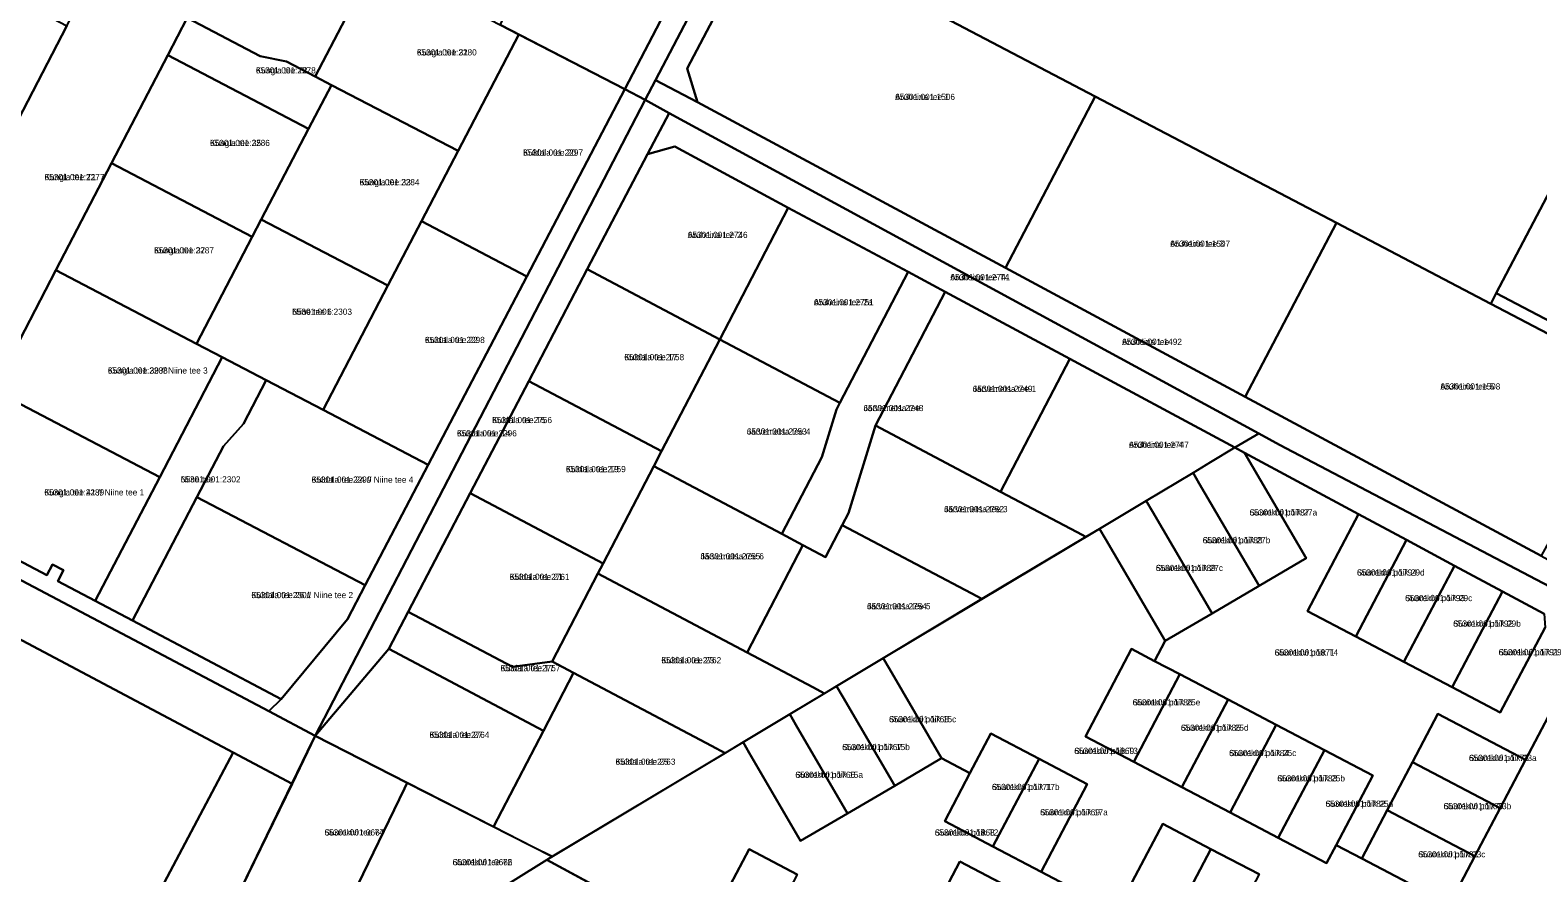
# Model space of a CAD drawing. Extents: x 543236 to 563717, y 6566033 to 6588992.
# Drawn here: x 545424.5 to 545789.8, y 6585039 to 6585243.3 of the extents above; entities that cross this region are included whole.
import ezdxf

# ---------------------------------------------------------------- set-up
doc = ezdxf.new("R2010")
doc.units = 0
for name, color, linetype in [('L_AADRESS', 7, 'Continuous'), ('PIIR', 7, 'Continuous'), ('TUNNUS', 7, 'Continuous')]:
    doc.layers.add(name, color=color, linetype=linetype)

msp = doc.modelspace()

# ---------------------------------------------------------------- linework, layer by layer
at = {"layer": 'PIIR'}
for points in [[(545810.82, 6585238.87), (545779.7, 6585179.53), (545778.37, 6585177), (545741, 6585196.59), (545682.55, 6585227.24), (545645.88, 6585246.47), (545647.21, 6585249.01), (545678.33, 6585308.34), (545709.67, 6585368.12), (545717.64, 6585363.94), (545697.05, 6585324.68), (545770.56, 6585286.13), (545782.51, 6585308.92), (545737.33, 6585384.25), (545731.7, 6585373.51), (545724.61, 6585377.23), (545720.43, 6585369.26), (545712.47, 6585373.43), (545743.84, 6585433.2)], [(545791.29, 6585101.79), (545781.2, 6585107.22), (545769.57, 6585113.48), (545757.95, 6585119.74), (545746.33, 6585126), (545718.68, 6585140.88), (545716.37, 6585142.12), (545722.15, 6585145.58), (545727.2, 6585142.83), (545794.29, 6585107.55)], [(545793.06, 6585078.35), (545786.77, 6585066.38), (545765.53, 6585077.56), (545759.38, 6585065.87), (545753.24, 6585054.19), (545747.1, 6585042.51), (545740.9, 6585045.76), (545749.75, 6585062.58), (545738.06, 6585068.72), (545726.38, 6585074.87), (545714.7, 6585081.01), (545703.02, 6585087.16), (545696.9, 6585090.37), (545699.46, 6585095.24), (545710.84, 6585101.92), (545722.22, 6585108.61), (545733.61, 6585115.29), (545718.68, 6585140.88), (545746.33, 6585126), (545733.95, 6585102.45), (545745.63, 6585096.31), (545757.31, 6585090.16), (545768.99, 6585084.02), (545780.68, 6585077.87), (545791.54, 6585098.53)], [(545722.25, 6585038.66), (545710.56, 6585044.78), (545698.87, 6585050.92), (545687.69, 6585029.64), (545669.41, 6585039.22), (545680.61, 6585060.53), (545668.93, 6585066.67), (545657.25, 6585072.81), (545652.18, 6585063.17), (545645.31, 6585066.78), (545632.67, 6585088.45), (545631.15, 6585091.04), (545683.58, 6585122.46), (545685.09, 6585119.87), (545699.46, 6585095.24), (545696.9, 6585090.37), (545691.33, 6585093.3), (545680.16, 6585072.06), (545691.85, 6585065.92), (545703.53, 6585059.77), (545715.21, 6585053.63), (545726.89, 6585047.48), (545738.58, 6585041.34), (545740.9, 6585045.76), (545747.1, 6585042.51), (545768.34, 6585031.33)], [(545796.96, 6585037.66), (545770.02, 6584986.31), (545766.77, 6584980.11), (545760.64, 6584968.42), (545754.51, 6584956.73), (545748.38, 6584945.04), (545745.2, 6584938.99), (545735.06, 6584944.32), (545725.29, 6584949.46), (545714.15, 6584953.57), (545719.21, 6584957.4), (545726.9, 6584963.24), (545735.97, 6584980.49), (545740.39, 6584978.17), (545746.53, 6584989.85), (545752.67, 6585001.54), (545758.81, 6585013.22), (545768.34, 6585031.33), (545774.48, 6585043.02), (545780.63, 6585054.7), (545786.77, 6585066.38), (545793.06, 6585078.35)], [(545586.73, 6585022.12), (545549.62, 6585042.17), (545597.19, 6585070.68), (545598.7, 6585068.09), (545611.14, 6585046.77), (545622.54, 6585053.42), (545633.93, 6585060.1), (545645.31, 6585066.78), (545652.18, 6585063.17), (545646.05, 6585051.51), (545657.73, 6585045.37), (545669.41, 6585039.22), (545687.69, 6585029.64)], [(545610.33, 6585038.63), (545598.65, 6585044.77), (545587.93, 6585024.39)]]:
    msp.add_lwpolyline(points, dxfattribs=at)
for points in [[(545576.01, 6585231.19), (545655.16, 6585382.35), (545660.23, 6585379.39), (545678.51, 6585414.04), (545681.17, 6585412.64), (545671.71, 6585394.8), (545668.91, 6585389.49), (545663.77, 6585379.74), (545650.9, 6585355.37), (545648.25, 6585356.76), (545634.76, 6585331.19), (545603.5, 6585271.93), (545601, 6585267.13), (545583.64, 6585234.01), (545586.14, 6585225.85)], [(545573.51, 6585226.42), (545568.52, 6585229.01), (545590.66, 6585271.51), (545596.2, 6585282.16), (545612.83, 6585314.09), (545631.44, 6585349.49), (545650.21, 6585385.19), (545655.16, 6585382.35), (545576.01, 6585231.19)], [(545455.85, 6585287.6), (545478.02, 6585276.05), (545462.53, 6585246.3), (545457.82, 6585237.26), (545444.19, 6585211.09), (545430.7, 6585185.18), (545415.55, 6585156.09), (545399.99, 6585126.22), (545377.89, 6585137.91), (545394.95, 6585170.65), (545416.76, 6585212.53), (545433.36, 6585244.41), (545438.07, 6585253.45)], [(545538.33, 6585244.64), (545560.5, 6585287.22), (545590.66, 6585271.51), (545568.52, 6585229.01)], [(545478.02, 6585276.05), (545508.18, 6585260.35), (545493.48, 6585232.12), (545486.61, 6585235.72), (545480.17, 6585237.06), (545462.53, 6585246.3)], [(545601, 6585267.13), (545629.11, 6585252.39), (545630.3, 6585254.64), (545645.88, 6585246.47), (545682.55, 6585227.24), (545660.76, 6585185.7), (545586.14, 6585225.85), (545583.64, 6585234.01)], [(545402.76, 6585260.48), (545433.36, 6585244.41), (545416.76, 6585212.53), (545386.12, 6585228.55)], [(545508.18, 6585260.35), (545538.33, 6585244.64), (545542.85, 6585242.29), (545528.15, 6585214.06), (545497.44, 6585230.04), (545493.48, 6585232.12)], [(545462.53, 6585246.3), (545480.17, 6585237.06), (545486.61, 6585235.72), (545493.48, 6585232.12), (545497.44, 6585230.04), (545491.9, 6585219.4), (545457.82, 6585237.26)], [(545542.85, 6585242.29), (545568.52, 6585229.01), (545544.79, 6585183.6), (545519.29, 6585197.06), (545528.15, 6585214.06)], [(545779.7, 6585179.53), (545810.82, 6585238.87), (545852.8, 6585216.85), (545855.46, 6585215.46), (545824.53, 6585156.02)], [(545457.82, 6585237.26), (545491.9, 6585219.4), (545480.44, 6585197.4), (545478.27, 6585193.23), (545444.19, 6585211.09)], [(545497.44, 6585230.04), (545528.15, 6585214.06), (545519.29, 6585197.06), (545511.15, 6585181.42), (545480.44, 6585197.4), (545491.9, 6585219.4)], [(545573.51, 6585226.42), (545576.01, 6585231.19), (545586.14, 6585225.85), (545660.76, 6585185.7), (545718.88, 6585154.42), (545790.6, 6585115.84), (545795.45, 6585113.23), (545805.7, 6585107.83), (545803.14, 6585102.9), (545794.29, 6585107.55), (545727.2, 6585142.83), (545722.15, 6585145.58), (545579.26, 6585223.25)], [(545196.2, 6585229.84), (545231.09, 6585211.25), (545291.43, 6585179.1), (545482.25, 6585078.21), (545493.54, 6585072.24), (545487.93, 6585060.63), (545473.62, 6585068.23), (545384.58, 6585115.49), (545368.67, 6585123.92), (545196.85, 6585214.99)], [(545568.52, 6585229.01), (545573.51, 6585226.42), (545493.54, 6585072.24), (545482.25, 6585078.21), (545485.31, 6585081.11), (545501.37, 6585100.52), (545505.66, 6585108.74), (545520.92, 6585137.92), (545544.79, 6585183.6)], [(545573.51, 6585226.42), (545579.26, 6585223.25), (545574.05, 6585213.28), (545559.45, 6585185.35), (545545.3, 6585158.27), (545531.1, 6585131.11), (545516.06, 6585102.34), (545511.34, 6585093.29), (545493.54, 6585072.24)], [(545660.76, 6585185.7), (545682.55, 6585227.24), (545741, 6585196.59), (545718.88, 6585154.42)], [(545579.26, 6585223.25), (545722.15, 6585145.58), (545716.37, 6585142.12), (545676.36, 6585163.64), (545646.17, 6585179.87), (545637.19, 6585184.71), (545608.13, 6585200.3), (545580.63, 6585215.14), (545574.05, 6585213.28)], [(545574.05, 6585213.28), (545580.63, 6585215.14), (545608.13, 6585200.3), (545591.53, 6585168.36), (545559.45, 6585185.35)], [(545444.19, 6585211.09), (545478.27, 6585193.23), (545464.78, 6585167.32), (545430.7, 6585185.18)], [(545480.44, 6585197.4), (545511.15, 6585181.42), (545495.44, 6585151.26), (545481.65, 6585158.49), (545471.02, 6585164.06), (545464.78, 6585167.32), (545478.27, 6585193.23)], [(545608.13, 6585200.3), (545637.19, 6585184.71), (545620.68, 6585152.94), (545591.53, 6585168.36)], [(545519.29, 6585197.06), (545544.79, 6585183.6), (545520.92, 6585137.92), (545495.44, 6585151.26), (545511.15, 6585181.42)], [(545718.88, 6585154.42), (545741, 6585196.59), (545778.37, 6585177), (545793.96, 6585168.82), (545792.78, 6585166.57), (545822.04, 6585151.22), (545803.95, 6585116.5), (545793.81, 6585121.8), (545790.6, 6585115.84)], [(545293.31, 6585182.63), (545295.64, 6585181.4), (545297.17, 6585184.32), (545299.87, 6585182.89), (545298.35, 6585179.97), (545347.41, 6585154.07), (545377.89, 6585137.91), (545399.99, 6585126.22), (545428.49, 6585111.16), (545429.86, 6585113.8), (545432.56, 6585112.37), (545431.19, 6585109.73), (545440.23, 6585104.95), (545449.25, 6585100.18), (545485.31, 6585081.11), (545482.25, 6585078.21), (545291.43, 6585179.1), (545291.9, 6585179.98)], [(545430.7, 6585185.18), (545464.78, 6585167.32), (545471.02, 6585164.06), (545455.86, 6585134.97), (545415.55, 6585156.09)], [(545559.45, 6585185.35), (545591.53, 6585168.36), (545577.44, 6585141.26), (545545.3, 6585158.27)], [(545637.19, 6585184.71), (545646.17, 6585179.87), (545629.32, 6585147.46), (545622.74, 6585126.23), (545621.23, 6585123.34), (545617.21, 6585115.59), (545611.71, 6585118.5), (545606.61, 6585121.2), (545616.27, 6585139.79), (545619.85, 6585151.34), (545620.68, 6585152.94)], [(545646.17, 6585179.87), (545676.36, 6585163.64), (545659.61, 6585131.42), (545629.32, 6585147.46)], [(545778.37, 6585177), (545779.7, 6585179.53), (545824.53, 6585156.02), (545822.04, 6585151.22), (545792.78, 6585166.57), (545793.96, 6585168.82)], [(545591.53, 6585168.36), (545620.68, 6585152.94), (545619.85, 6585151.34), (545616.27, 6585139.79), (545606.61, 6585121.2), (545575.56, 6585137.63), (545577.44, 6585141.26)], [(545471.02, 6585164.06), (545481.65, 6585158.49), (545476.13, 6585147.91), (545471.27, 6585142.46), (545464.84, 6585130.13), (545449.25, 6585100.18), (545440.23, 6585104.95), (545455.86, 6585134.97)], [(545676.36, 6585163.64), (545716.37, 6585142.12), (545710.48, 6585138.59), (545706.22, 6585136.03), (545694.9, 6585129.25), (545683.58, 6585122.46), (545680.28, 6585120.49), (545678.18, 6585121.6), (545659.61, 6585131.42)], [(545481.65, 6585158.49), (545495.44, 6585151.26), (545520.92, 6585137.92), (545505.66, 6585108.74), (545464.84, 6585130.13), (545471.27, 6585142.46), (545476.13, 6585147.91)], [(545545.3, 6585158.27), (545577.44, 6585141.26), (545575.56, 6585137.63), (545563.31, 6585114.06), (545531.1, 6585131.11)], [(545415.55, 6585156.09), (545455.86, 6585134.97), (545440.23, 6585104.95), (545431.19, 6585109.73), (545432.56, 6585112.37), (545429.86, 6585113.8), (545428.49, 6585111.16), (545399.99, 6585126.22)], [(545629.32, 6585147.46), (545659.61, 6585131.42), (545678.18, 6585121.6), (545680.28, 6585120.49), (545655.05, 6585105.45), (545652.5, 6585106.8), (545621.23, 6585123.34), (545622.74, 6585126.23)], [(545706.22, 6585136.03), (545710.48, 6585138.59), (545716.37, 6585142.12), (545718.68, 6585140.88), (545733.61, 6585115.29), (545722.22, 6585108.61), (545707.73, 6585133.44)], [(545575.56, 6585137.63), (545606.61, 6585121.2), (545611.71, 6585118.5), (545598.16, 6585092.42), (545562, 6585111.56), (545563.31, 6585114.06)], [(545694.9, 6585129.25), (545706.22, 6585136.03), (545707.73, 6585133.44), (545722.22, 6585108.61), (545710.84, 6585101.92), (545696.41, 6585126.66)], [(545464.84, 6585130.13), (545505.66, 6585108.74), (545501.37, 6585100.52), (545485.31, 6585081.11), (545449.25, 6585100.18)], [(545531.1, 6585131.11), (545563.31, 6585114.06), (545562, 6585111.56), (545550.92, 6585090.24), (545541.34, 6585088.96), (545516.06, 6585102.34)], [(545683.58, 6585122.46), (545694.9, 6585129.25), (545696.41, 6585126.66), (545710.84, 6585101.92), (545699.46, 6585095.24), (545685.09, 6585119.87)], [(545746.33, 6585126), (545757.95, 6585119.74), (545745.63, 6585096.31), (545733.95, 6585102.45)], [(545611.71, 6585118.5), (545617.21, 6585115.59), (545621.23, 6585123.34), (545652.5, 6585106.8), (545655.05, 6585105.45), (545631.15, 6585091.04), (545619.83, 6585084.25), (545616.91, 6585082.5), (545614.08, 6585084), (545598.16, 6585092.42)], [(545757.95, 6585119.74), (545769.57, 6585113.48), (545757.31, 6585090.16), (545745.63, 6585096.31)], [(545473.62, 6585068.23), (545439.46, 6585003.59), (545451.28, 6584984.82), (545449.99, 6584982.15), (545421.27, 6584965.16), (545372.09, 6584935.15), (545368.98, 6584936.89), (545361.63, 6584940.84), (545358.12, 6584942.6), (545293.55, 6584977.38), (545384.58, 6585115.49)], [(545769.57, 6585113.48), (545781.2, 6585107.22), (545768.99, 6585084.02), (545757.31, 6585090.16)], [(545562, 6585111.56), (545598.16, 6585092.42), (545614.08, 6585084), (545616.91, 6585082.5), (545608.51, 6585077.47), (545597.19, 6585070.68), (545592.83, 6585068.07), (545589.54, 6585069.81), (545556.12, 6585087.49), (545550.92, 6585090.24)], [(545781.2, 6585107.22), (545791.29, 6585101.79), (545791.54, 6585098.53), (545780.68, 6585077.87), (545768.99, 6585084.02)], [(545516.06, 6585102.34), (545541.34, 6585088.96), (545550.92, 6585090.24), (545556.12, 6585087.49), (545548.83, 6585073.45), (545511.34, 6585093.29)], [(545511.34, 6585093.29), (545548.83, 6585073.45), (545536.73, 6585050.18), (545515.81, 6585060.87), (545493.54, 6585072.24)], [(545691.33, 6585093.3), (545696.9, 6585090.37), (545703.02, 6585087.16), (545691.85, 6585065.92), (545680.16, 6585072.06)], [(545619.83, 6585084.25), (545631.15, 6585091.04), (545632.67, 6585088.45), (545645.31, 6585066.78), (545633.93, 6585060.1), (545621.34, 6585081.66)], [(545556.12, 6585087.49), (545589.54, 6585069.81), (545592.83, 6585068.07), (545550.91, 6585042.94), (545546.53, 6585045.18), (545536.73, 6585050.18), (545548.83, 6585073.45)], [(545608.51, 6585077.47), (545619.83, 6585084.25), (545621.34, 6585081.66), (545633.93, 6585060.1), (545622.54, 6585053.42), (545610.02, 6585074.87)], [(545703.02, 6585087.16), (545714.7, 6585081.01), (545703.53, 6585059.77), (545691.85, 6585065.92)], [(545714.7, 6585081.01), (545726.38, 6585074.87), (545715.21, 6585053.63), (545703.53, 6585059.77)], [(545597.19, 6585070.68), (545608.51, 6585077.47), (545610.02, 6585074.87), (545622.54, 6585053.42), (545611.14, 6585046.77), (545598.7, 6585068.09)], [(545765.53, 6585077.56), (545786.77, 6585066.38), (545780.63, 6585054.7), (545759.38, 6585065.87)], [(545726.38, 6585074.87), (545738.06, 6585068.72), (545726.89, 6585047.48), (545715.21, 6585053.63)], [(545493.54, 6585072.24), (545515.81, 6585060.87), (545515.15, 6585059.5), (545500.12, 6585028.41), (545512.27, 6585022.16), (545514.85, 6585020.84), (545509.79, 6585017.81), (545507.34, 6585019.08), (545475.7, 6585035.34), (545492.9, 6585070.91)], [(545657.25, 6585072.81), (545668.93, 6585066.67), (545657.73, 6585045.37), (545646.05, 6585051.51), (545652.18, 6585063.17)], [(545473.62, 6585068.23), (545487.93, 6585060.63), (545475.7, 6585035.34), (545459.19, 6585001.19), (545451.9, 6584986.11), (545451.28, 6584984.82), (545439.46, 6585003.59)], [(545668.93, 6585066.67), (545680.61, 6585060.53), (545669.41, 6585039.22), (545657.73, 6585045.37)], [(545738.06, 6585068.72), (545749.75, 6585062.58), (545740.9, 6585045.76), (545738.58, 6585041.34), (545726.89, 6585047.48)], [(545759.38, 6585065.87), (545780.63, 6585054.7), (545774.48, 6585043.02), (545753.24, 6585054.19)], [(545515.81, 6585060.87), (545550.91, 6585042.94), (545549.62, 6585042.17), (545525.19, 6585026.92), (545514.85, 6585020.84), (545512.27, 6585022.16), (545500.12, 6585028.41), (545515.15, 6585059.5)], [(545753.24, 6585054.19), (545774.48, 6585043.02), (545768.34, 6585031.33), (545747.1, 6585042.51)], [(545698.87, 6585050.92), (545710.56, 6585044.78), (545699.37, 6585023.51), (545687.69, 6585029.64)], [(545598.65, 6585044.77), (545610.33, 6585038.63), (545599.54, 6585018.11), (545598.92, 6585015.53), (545586.73, 6585022.12), (545587.93, 6585024.39)], [(545710.56, 6585044.78), (545722.25, 6585038.66), (545711.06, 6585017.38), (545699.37, 6585023.51)], [(545549.62, 6585042.17), (545570.85, 6585030.7), (545569.63, 6585028.37), (545556.58, 6585003.22), (545526.38, 6585018.89), (545525.92, 6585022.04), (545525.19, 6585026.92)], [(545649.71, 6585041.75), (545643.56, 6585030.07), (545637.42, 6585018.39), (545631.28, 6585006.7), (545652.52, 6584995.53), (545658.66, 6585007.22), (545664.8, 6585018.9), (545670.95, 6585030.58)], [(545649.71, 6585041.75), (545670.95, 6585030.58), (545664.8, 6585018.9), (545643.56, 6585030.07)]]:
    msp.add_lwpolyline(points, close=True, dxfattribs=at)

# ---------------------------------------------------------------- texts
at = {"layer": 'L_AADRESS'}
for s, p in [('Kungla tee 31', (545518.16, 6585237.21)), ('Kungla tee T2', (545479.16, 6585232.85)), ('Aruheina tee 1', (545634.04, 6585226.41)), ('Kungla tee 35', (545468.04, 6585215.25)), ('Kuldala tee 20', (545543.91, 6585212.91)), ('Kungla tee T1', (545427.96, 6585206.97)), ('Kungla tee 33', (545504.29, 6585205.73)), ('Aruheina tee 2', (545583.79, 6585192.95)), ('Kungla tee 37', (545454.49, 6585189.21)), ('Aruheina tee 3', (545700.71, 6585190.83)), ('Aruheina tee T4', (545647.42, 6585182.69)), ('Niine tee 6', (545487.94, 6585174.33)), ('Aruheina tee 2a', (545614.36, 6585176.62)), ('Kuldala tee 22', (545520.11, 6585167.48)), ('Aruheina tee', (545689.04, 6585167.04)), ('Kuldala tee 17', (545568.42, 6585163.31)), ('Kungla tee 39 // Niine tee 3', (545443.28, 6585160.07)), ('Järvemetsa tee 1', (545652.84, 6585155.64)), ('Aruheina tee 5', (545766.17, 6585156.21)), ('Kuldala tee T5', (545536.4, 6585148.06)), ('Järvemetsa tee', (545626.39, 6585150.97)), ('Kuldala tee T4', (545527.88, 6585144.84)), ('Järvemetsa tee 4', (545598.12, 6585145.28)), ('Aruheina tee 4', (545690.71, 6585142.07)), ('Niine tee', (545460.94, 6585133.68)), ('Kuldala tee 24 // Niine tee 4', (545492.66, 6585133.61)), ('Kuldala tee 19', (545554.27, 6585136.16)), ('Kungla tee 41 // Niine tee 1', (545427.89, 6585130.52)), ('Järvemetsa tee 3', (545645.9, 6585126.46)), ('Suurekivi põik 27a', (545719.91, 6585125.66)), ('Suurekivi põik 27b', (545708.56, 6585118.92)), ('Järvemetsa tee 6', (545586.86, 6585115.03)), ('Suurekivi põik 27c', (545697.21, 6585112.19)), ('Kuldala tee 21', (545540.65, 6585110.04)), ('Suurekivi põik 29d', (545745.95, 6585111.1)), ('Kuldala tee 26 // Niine tee 2', (545478.06, 6585105.62)), ('Suurekivi põik 29c', (545757.6, 6585104.89)), ('Järvemetsa tee 5', (545627.23, 6585102.92)), ('Suurekivi põik 29b', (545769.26, 6585098.7)), ('Kuldala tee 23', (545577.4, 6585089.82)), ('Suurekivi põik T4', (545726, 6585091.7)), ('Suurekivi põik 29a', (545780.27, 6585091.77)), ('Kuldala tee T7', (545538.44, 6585087.9)), ('Suurekivi põik 25e', (545691.59, 6585079.61)), ('Suurekivi põik 15c', (545632.57, 6585075.52)), ('Kuldala tee 27', (545521.23, 6585071.74)), ('Suurekivi põik 25d', (545703.28, 6585073.46)), ('Suurekivi põik 15b', (545621.22, 6585068.77)), ('Suurekivi põik T3', (545677.45, 6585067.84)), ('Kuldala tee 25', (545566.31, 6585065.21)), ('Suurekivi põik 25c', (545714.96, 6585067.32)), ('Suurekivi põik 23a', (545773.08, 6585066.13)), ('Suurekivi põik 15a', (545609.86, 6585062.05)), ('Suurekivi põik 25b', (545726.64, 6585061.18)), ('Suurekivi põik 17b', (545657.49, 6585059.09)), ('Suurekivi põik 25a', (545738.32, 6585055.03)), ('Suurekivi põik 23b', (545766.93, 6585054.45)), ('Suurekivi põik 17a', (545669.17, 6585052.95)), ('Suurekivi tee 74', (545495.76, 6585048.07)), ('Suurekivi põik T2', (545643.66, 6585048.04)), ('Suurekivi põik 23c', (545760.79, 6585042.76)), ('Suurekivi tee 72', (545526.82, 6585040.86))]:
    msp.add_text(s, height=1.5, dxfattribs=at).set_placement(p)
at = {"layer": 'TUNNUS'}
for s, p in [('65301:001:2280', (545518.16, 6585237.21)), ('65301:001:2278', (545479.16, 6585232.85)), ('65301:001:1506', (545634.04, 6585226.41)), ('65301:001:2286', (545468.04, 6585215.25)), ('65301:001:2297', (545543.91, 6585212.91)), ('65301:001:2277', (545427.96, 6585206.97)), ('65301:001:2284', (545504.29, 6585205.73)), ('65301:001:2746', (545583.79, 6585192.95)), ('65301:001:2287', (545454.49, 6585189.21)), ('65301:001:1507', (545700.71, 6585190.83)), ('65301:001:2741', (545647.42, 6585182.69)), ('65301:001:2303', (545487.94, 6585174.33)), ('65301:001:2751', (545614.36, 6585176.62)), ('65301:001:2298', (545520.11, 6585167.48)), ('65301:001:1492', (545689.04, 6585167.04)), ('65301:001:2758', (545568.42, 6585163.31)), ('65301:001:2288', (545443.28, 6585160.07)), ('65301:001:2749', (545652.84, 6585155.64)), ('65301:001:1508', (545766.17, 6585156.21)), ('65301:001:2748', (545626.39, 6585150.97)), ('65301:001:2296', (545527.88, 6585144.84)), ('65301:001:2756', (545536.4, 6585148.06)), ('65301:001:2753', (545598.12, 6585145.28)), ('65301:001:2747', (545690.71, 6585142.07)), ('65301:001:2302', (545460.94, 6585133.68)), ('65301:001:2299', (545492.66, 6585133.61)), ('65301:001:2759', (545554.27, 6585136.16)), ('65301:001:2289', (545427.89, 6585130.52)), ('65301:001:2752', (545645.9, 6585126.46)), ('65301:001:1787', (545719.91, 6585125.66)), ('65301:001:1788', (545708.56, 6585118.92)), ('65301:001:2755', (545586.86, 6585115.03)), ('65301:001:1789', (545697.21, 6585112.19)), ('65301:001:2761', (545540.65, 6585110.04)), ('65301:001:1794', (545745.95, 6585111.1)), ('65301:001:2301', (545478.06, 6585105.62)), ('65301:001:1793', (545757.6, 6585104.89)), ('65301:001:2754', (545627.23, 6585102.92)), ('65301:001:1792', (545769.26, 6585098.7)), ('65301:001:2762', (545577.4, 6585089.82)), ('65301:001:1871', (545726, 6585091.7)), ('65301:001:1791', (545780.27, 6585091.77)), ('65301:001:2757', (545538.44, 6585087.9)), ('65301:001:1786', (545691.59, 6585079.61)), ('65301:001:1768', (545632.57, 6585075.52)), ('65301:001:2764', (545521.23, 6585071.74)), ('65301:001:1785', (545703.28, 6585073.46)), ('65301:001:1767', (545621.22, 6585068.77)), ('65301:001:1869', (545677.45, 6585067.84)), ('65301:001:2763', (545566.31, 6585065.21)), ('65301:001:1784', (545714.96, 6585067.32)), ('65301:001:1778', (545773.08, 6585066.13)), ('65301:001:1766', (545609.86, 6585062.05)), ('65301:001:1783', (545726.64, 6585061.18)), ('65301:001:1771', (545657.49, 6585059.09)), ('65301:001:1782', (545738.32, 6585055.03)), ('65301:001:1779', (545766.93, 6585054.45)), ('65301:001:1769', (545669.17, 6585052.95)), ('65301:001:0667', (545495.76, 6585048.07)), ('65301:001:1868', (545643.66, 6585048.04)), ('65301:001:1781', (545760.79, 6585042.76)), ('65301:001:0666', (545526.82, 6585040.86))]:
    msp.add_text(s, height=1.5, dxfattribs=at).set_placement(p)

doc.saveas('drawing.dxf')
